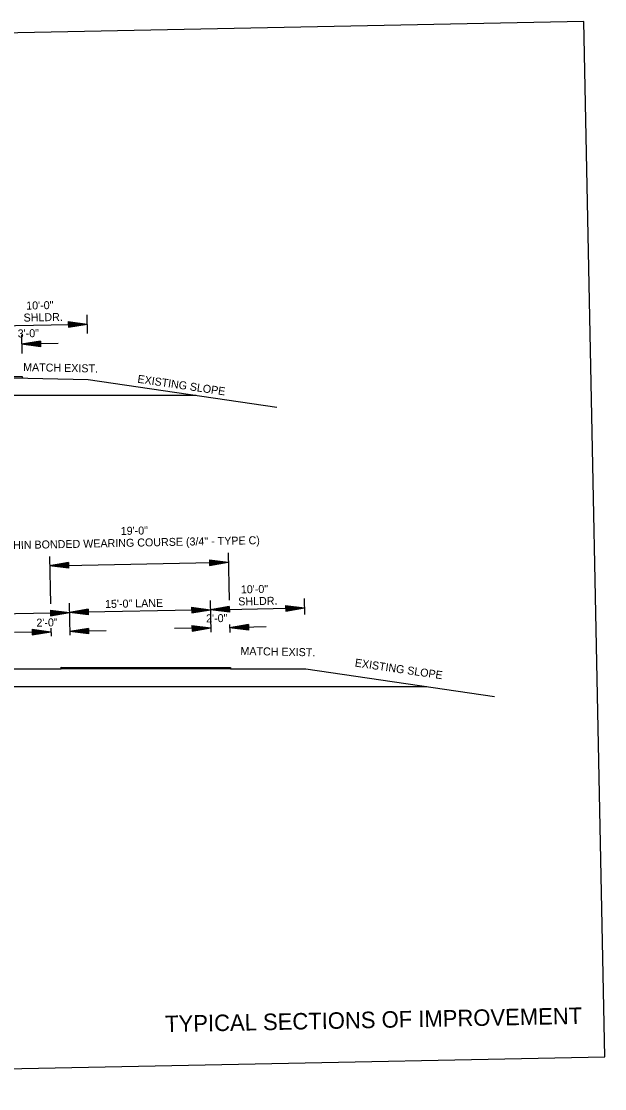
# Model space of a CAD drawing. Extents: x 174 to 869, y -36 to 177.
# Drawn here: x 283.7 to 345.7, y 53.6 to 167 of the extents above; entities that cross this region are included whole.
import ezdxf

# ---------------------------------------------------------------- set-up
doc = ezdxf.new("R2010")
doc.units = 0
for name, color, linetype in [('DSN_DRFT_Common-Annotations', 7, 'Continuous'), ('DSN_DRFT_Common-Line', 7, 'Continuous'), ('DSN_DRFT_Dimension', 7, 'Continuous'), ('SHET_Border-Text', 7, 'Continuous')]:
    doc.layers.add(name, color=color, linetype=linetype)

msp = doc.modelspace()

# ---------------------------------------------------------------- linework, layer by layer
at = {"layer": 'DSN_DRFT_Common-Line'}
for p, q in [((290.65, 135.82), (290.69, 133.82)), ((283.69, 133.68), (283.73, 131.68)), ((280.79, 129.14), (290.79, 128.94)), ((290.79, 128.94), (310.85, 126.01)), ((256.82, 127.27), (302.25, 127.27)), ((286.66, 110.14), (286.76, 105.12)), ((305.66, 110.52), (305.76, 105.5)), ((303.76, 105.46), (303.83, 102.09)), ((313.76, 105.68), (313.79, 103.97)), ((288.76, 105.16), (288.83, 101.79)), ((286.82, 102.52), (286.83, 101.68)), ((305.81, 102.9), (305.83, 102.06)), ((266.9, 98.2), (287.9, 98.2)), ((305.91, 98.2), (313.91, 98.2)), ((313.91, 98.2), (333.97, 95.27)), ((239.93, 96.32), (326.77, 96.32))]:
    msp.add_line(p, q, dxfattribs=at)
for points in [[(173.52, 163.58), (175.72, 53.6), (345.69, 57), (343.49, 166.98)], [(280.79, 129.14), (256.78, 129.14), (244.79, 128.66), (241.79, 128.54), (241.79, 128.71), (244.78, 128.83), (256.78, 129.31), (280.78, 129.31), (283.78, 129.25), (283.79, 129.08)], [(305.91, 98.2), (287.9, 98.2), (287.9, 98.2), (287.9, 98.2), (287.9, 98.36), (287.9, 98.36), (287.9, 98.36), (305.91, 98.35), (305.91, 98.35), (305.91, 98.2)]]:
    msp.add_lwpolyline(points, close=True, dxfattribs=at)
at = {"layer": 'DSN_DRFT_Dimension'}
for p, q in [((288.67, 135.08), (290.67, 134.82)), ((288.67, 135.08), (288.68, 134.48)), ((288.67, 135.03), (290.34, 134.81)), ((288.67, 134.98), (290, 134.81)), ((288.67, 134.93), (289.66, 134.8)), ((280.68, 134.62), (290.67, 134.82)), ((288.67, 134.88), (289.32, 134.79)), ((288.67, 134.83), (288.99, 134.79)), ((288.67, 134.73), (288.99, 134.79)), ((288.68, 134.48), (290.67, 134.82)), ((288.68, 134.58), (290, 134.81)), ((288.68, 134.53), (290.34, 134.81)), ((288.68, 134.63), (289.66, 134.8)), ((288.68, 134.68), (289.32, 134.79)), ((285.71, 133.02), (283.71, 132.68)), ((287.58, 132.76), (283.71, 132.68)), ((285.72, 132.42), (283.71, 132.68)), ((285.71, 132.97), (284.05, 132.69)), ((285.72, 132.47), (284.05, 132.69)), ((285.71, 132.92), (284.39, 132.69)), ((285.72, 132.52), (284.39, 132.69)), ((285.71, 132.87), (284.73, 132.7)), ((285.72, 132.57), (284.73, 132.7)), ((285.71, 132.82), (285.06, 132.71)), ((285.72, 132.62), (285.06, 132.71)), ((285.71, 132.77), (285.4, 132.71)), ((285.72, 132.67), (285.4, 132.71)), ((285.71, 133.02), (285.72, 132.42)), ((286.68, 109.14), (305.68, 109.52)), ((288.68, 109.48), (286.68, 109.14)), ((288.69, 108.88), (286.68, 109.14)), ((288.68, 109.43), (287.02, 109.14)), ((288.69, 108.93), (287.02, 109.14)), ((288.68, 109.37), (287.36, 109.15)), ((288.69, 108.98), (287.36, 109.15)), ((288.68, 109.32), (287.69, 109.16)), ((288.69, 109.03), (287.69, 109.16)), ((288.68, 109.27), (288.03, 109.16)), ((288.69, 109.08), (288.03, 109.16)), ((288.68, 109.22), (288.37, 109.17)), ((288.68, 109.13), (288.37, 109.17)), ((288.68, 109.48), (288.69, 108.88)), ((303.68, 109.78), (305.68, 109.52)), ((303.68, 109.78), (303.69, 109.18)), ((303.68, 109.73), (305.35, 109.51)), ((303.68, 109.67), (305, 109.5)), ((303.68, 109.62), (304.67, 109.5)), ((303.68, 109.57), (304.33, 109.49)), ((303.68, 109.52), (304, 109.48)), ((303.68, 109.38), (304.33, 109.49)), ((303.68, 109.43), (304, 109.48)), ((303.69, 109.18), (305.68, 109.52)), ((303.69, 109.23), (305.35, 109.51)), ((303.69, 109.28), (305, 109.5)), ((303.69, 109.33), (304.67, 109.5)), ((286.78, 104.44), (288.78, 104.18)), ((286.78, 104.44), (286.79, 103.84)), ((286.78, 104.39), (288.45, 104.17)), ((286.78, 104.34), (288.11, 104.16)), ((290.78, 104.52), (288.78, 104.18)), ((303.78, 104.48), (288.78, 104.18)), ((290.78, 104.47), (289.12, 104.18)), ((290.78, 104.42), (289.46, 104.19)), ((290.78, 104.37), (289.8, 104.2)), ((290.78, 104.31), (290.13, 104.2)), ((290.78, 104.52), (290.79, 103.92)), ((301.78, 104.74), (303.78, 104.48)), ((301.78, 104.74), (301.79, 104.14)), ((301.78, 104.69), (303.45, 104.47)), ((301.78, 104.64), (303.1, 104.46)), ((301.78, 104.59), (302.77, 104.46)), ((301.78, 104.53), (302.43, 104.45)), ((301.78, 104.48), (302.1, 104.44)), ((301.78, 104.29), (302.77, 104.46)), ((301.78, 104.34), (302.43, 104.45)), ((301.78, 104.39), (302.1, 104.44)), ((301.79, 104.14), (303.78, 104.48)), ((301.79, 104.19), (303.45, 104.47)), ((301.79, 104.24), (303.1, 104.46)), ((305.77, 104.82), (303.78, 104.48)), ((303.78, 104.48), (313.78, 104.68)), ((305.79, 104.22), (303.78, 104.48)), ((305.78, 104.77), (304.12, 104.48)), ((305.79, 104.27), (304.12, 104.48)), ((305.78, 104.72), (304.46, 104.49)), ((305.78, 104.32), (304.46, 104.49)), ((305.78, 104.67), (304.79, 104.5)), ((305.78, 104.37), (304.79, 104.5)), ((305.78, 104.61), (305.13, 104.5)), ((305.78, 104.42), (305.13, 104.5)), ((305.78, 104.56), (305.46, 104.51)), ((305.78, 104.47), (305.46, 104.51)), ((305.77, 104.82), (305.79, 104.22)), ((311.77, 104.94), (313.78, 104.68)), ((311.77, 104.94), (311.79, 104.34)), ((311.77, 104.89), (313.45, 104.67)), ((311.78, 104.84), (313.1, 104.66)), ((311.78, 104.79), (312.77, 104.66)), ((311.78, 104.73), (312.43, 104.65)), ((311.78, 104.68), (312.1, 104.64)), ((311.78, 104.39), (313.45, 104.67)), ((311.78, 104.44), (313.1, 104.66)), ((311.78, 104.49), (312.77, 104.66)), ((311.78, 104.54), (312.43, 104.65)), ((311.78, 104.59), (312.1, 104.64)), ((311.79, 104.34), (313.78, 104.68)), ((263.79, 103.68), (288.78, 104.18)), ((286.78, 104.29), (287.77, 104.16)), ((286.78, 104.23), (287.43, 104.15)), ((286.78, 104.18), (287.1, 104.14)), ((286.79, 103.84), (288.78, 104.18)), ((286.79, 103.89), (288.45, 104.17)), ((286.79, 103.94), (288.11, 104.16)), ((286.79, 103.99), (287.77, 104.16)), ((286.79, 104.04), (287.43, 104.15)), ((286.79, 104.09), (287.1, 104.14)), ((290.79, 103.92), (288.78, 104.18)), ((290.79, 103.97), (289.12, 104.18)), ((290.79, 104.02), (289.46, 104.19)), ((290.79, 104.07), (289.8, 104.2)), ((290.79, 104.12), (290.13, 104.2)), ((290.78, 104.26), (290.47, 104.21)), ((290.78, 104.17), (290.47, 104.21)), ((286.82, 102.14), (282.96, 102.06)), ((284.82, 102.4), (286.82, 102.14)), ((284.82, 102.4), (284.83, 101.8)), ((284.82, 102.35), (286.49, 102.13)), ((284.82, 102.3), (286.15, 102.12)), ((284.82, 102.25), (285.81, 102.12)), ((284.82, 102.19), (285.47, 102.11)), ((284.82, 102.14), (285.14, 102.1)), ((284.82, 102.05), (285.14, 102.1)), ((284.83, 101.8), (286.82, 102.14)), ((284.83, 101.85), (286.49, 102.13)), ((284.83, 101.9), (286.15, 102.12)), ((284.83, 101.95), (285.81, 102.12)), ((284.83, 102), (285.47, 102.11)), ((290.82, 102.5), (288.82, 102.16)), ((292.69, 102.23), (288.82, 102.16)), ((290.83, 101.9), (288.82, 102.16)), ((290.82, 102.45), (289.16, 102.16)), ((290.83, 101.95), (289.16, 102.16)), ((290.82, 102.4), (289.5, 102.17)), ((290.83, 102), (289.5, 102.17)), ((290.82, 102.35), (289.84, 102.18)), ((290.83, 102.05), (289.84, 102.18)), ((290.82, 102.29), (290.17, 102.18)), ((290.83, 102.1), (290.17, 102.18)), ((290.82, 102.24), (290.51, 102.19)), ((290.83, 102.15), (290.51, 102.19)), ((290.82, 102.5), (290.83, 101.9)), ((303.82, 102.55), (299.96, 102.47)), ((301.81, 102.81), (303.82, 102.55)), ((301.81, 102.81), (301.83, 102.21)), ((301.82, 102.76), (303.49, 102.54)), ((301.82, 102.71), (303.14, 102.54)), ((301.82, 102.66), (302.81, 102.53)), ((301.82, 102.61), (302.47, 102.52)), ((301.82, 102.56), (302.14, 102.52)), ((301.82, 102.31), (303.14, 102.54)), ((301.82, 102.36), (302.81, 102.53)), ((301.82, 102.41), (302.47, 102.52)), ((301.82, 102.46), (302.14, 102.52)), ((301.83, 102.21), (303.82, 102.55)), ((301.83, 102.26), (303.49, 102.54)), ((307.81, 102.91), (305.82, 102.57)), ((309.69, 102.65), (305.82, 102.57)), ((307.83, 102.31), (305.82, 102.57)), ((307.82, 102.86), (306.15, 102.58)), ((307.83, 102.36), (306.15, 102.58)), ((307.82, 102.81), (306.5, 102.58)), ((307.82, 102.41), (306.5, 102.58)), ((307.82, 102.76), (306.83, 102.59)), ((307.82, 102.46), (306.83, 102.59)), ((307.82, 102.71), (307.17, 102.6)), ((307.82, 102.51), (307.17, 102.6)), ((307.82, 102.66), (307.5, 102.6)), ((307.82, 102.56), (307.5, 102.6)), ((307.81, 102.91), (307.83, 102.31))]:
    msp.add_line(p, q, dxfattribs=at)

# ---------------------------------------------------------------- texts
at = {"layer": 'DSN_DRFT_Common-Annotations'}
for s, rotation, p in [('10\'-0"', 1.1458, (284.2, 136.36)), ('SHLDR.', 1.1458, (283.92, 135.08)), (' 3\'-0"', 1.1458, (282.98, 133.39)), ('MATCH EXIST.', 358.8552, (283.86, 129.83)), ('EXISTING SLOPE', 351.6838, (295.98, 128.6)), ('ULTRATHIN BONDED WEARING COURSE (3/4" - TYPE C)', 1.1458, (278.39, 110.83)), ('19\'-0"', 1.1458, (294.25, 112.42)), ('10\'-0"', 1.1458, (307.02, 106.21)), ('15\'-0" LANE', 1.1458, (292.58, 104.66)), ('SHLDR.', 1.1458, (306.74, 104.93)), (' 2\'-0"', 1.1458, (284.97, 102.67)), (' 2\'-0"', 1.1458, (303.01, 103.12)), ('MATCH EXIST.', 358.8552, (306.96, 99.68)), ('EXISTING SLOPE', 351.6838, (319.09, 98.45))]:
    msp.add_text(s, height=0.85, rotation=rotation, dxfattribs=at).set_placement(p)
at = {"layer": 'SHET_Border-Text'}
msp.add_text('TYPICAL SECTIONS OF IMPROVEMENT', height=1.75, rotation=1.1458, dxfattribs=at).set_placement((298.98, 59.6))

doc.saveas('drawing.dxf')
